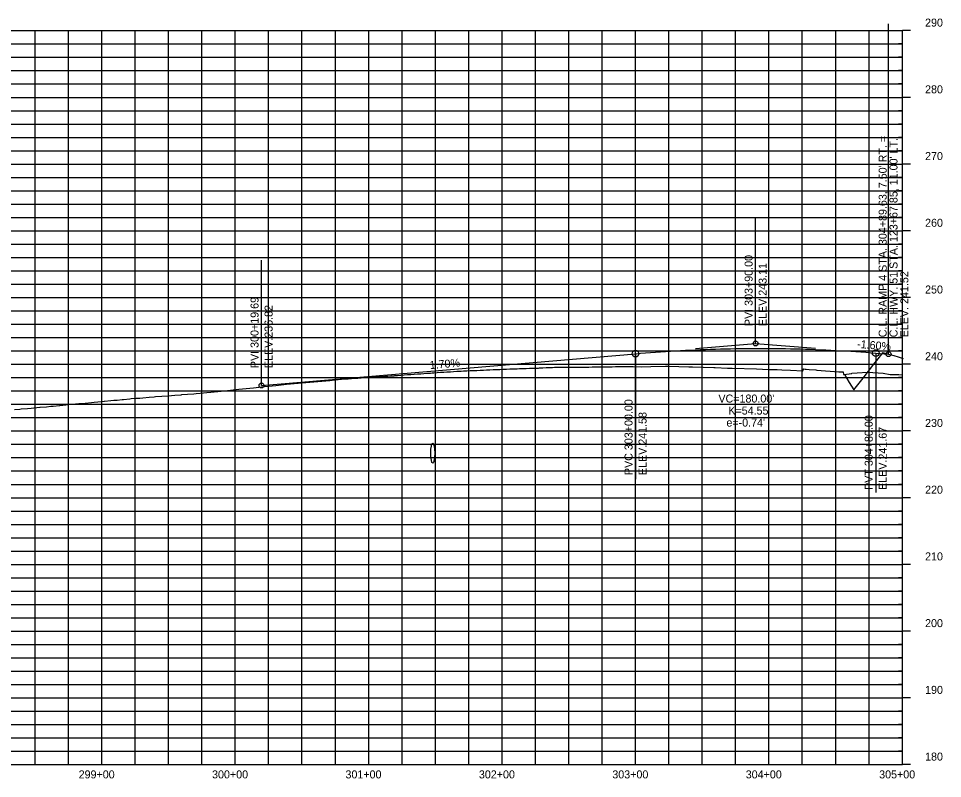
# Model space of a CAD drawing. Extents: x 921603 to 924670, y 1759276 to 1766491.
# Drawn here: x 922277 to 922970, y 1760922 to 1761491 of the extents above; entities that cross this region are included whole.
import ezdxf

# ---------------------------------------------------------------- set-up
doc = ezdxf.new("R2010")
doc.units = 0
for name, color, linetype in [('R_Axis_Annotation', 7, 'Continuous'), ('R_Drainage', 7, 'Continuous'), ('R_Exist Surface', 7, 'Continuous'), ('R_Grid', 7, 'Continuous'), ('R_Grid Annot', 7, 'Continuous'), ('R_Grid_Minor', 7, 'Continuous'), ('R_Prop Surface', 7, 'Continuous'), ('R_Vert Alg', 7, 'Continuous'), ('R_Vert Alg Annot', 7, 'Continuous')]:
    doc.layers.add(name, color=color, linetype=linetype)

msp = doc.modelspace()

# ---------------------------------------------------------------- linework, layer by layer
at = {"layer": 'R_Drainage'}
msp.add_ellipse((922587.83, 1761165.61), major_axis=(0, 7.5), ratio=0.2, dxfattribs=at)
at = {"layer": 'R_Exist Surface'}
msp.add_lwpolyline([(922274.45, 1761198.33), (922278.3, 1761198.63), (922279.25, 1761198.72), (922284.05, 1761199.17), (922286.72, 1761199.41), (922288.85, 1761199.6), (922293.27, 1761199.98), (922293.65, 1761200.02), (922298.45, 1761200.44), (922301.68, 1761200.73), (922303.24, 1761200.86), (922308.04, 1761201.25), (922308.23, 1761201.27), (922312.84, 1761201.8), (922317.37, 1761202.31), (922317.64, 1761202.33), (922322.44, 1761202.73), (922325.06, 1761202.94), (922327.24, 1761203.18), (922332.03, 1761203.7), (922334.06, 1761203.92), (922336.83, 1761204.14), (922341.63, 1761204.52), (922341.88, 1761204.54), (922346.43, 1761205.01), (922348.89, 1761205.27), (922351.23, 1761205.46), (922355.04, 1761205.77), (922356.03, 1761205.87), (922360.83, 1761206.36), (922361.91, 1761206.47), (922365.62, 1761206.76), (922368.2, 1761206.96), (922370.42, 1761207.16), (922375.22, 1761207.57), (922378.91, 1761207.89), (922380.02, 1761207.97), (922384.82, 1761208.31), (922389.39, 1761208.63), (922389.62, 1761208.65), (922394.41, 1761209.05), (922399.21, 1761209.44), (922399.79, 1761209.49), (922404.01, 1761209.78), (922408.81, 1761210.11), (922410.55, 1761210.23), (922413.61, 1761210.52), (922418.41, 1761210.99), (922421.44, 1761211.28), (922431.95, 1761212.38), (922442.41, 1761213.48), (922453.36, 1761214.53), (922461.65, 1761215.6), (922470.16, 1761216.31), (922478.28, 1761217.36), (922486.94, 1761218.08), (922498.77, 1761219.2), (922510.71, 1761220.13), (922514.45, 1761220.5), (922516.92, 1761220.74), (922519.39, 1761220.97), (922521.87, 1761221.2), (922523.66, 1761221.36), (922524.34, 1761221.41), (922526.81, 1761221.59), (922529.29, 1761221.76), (922531.76, 1761221.92), (922533.01, 1761222), (922534.23, 1761222.09), (922536.71, 1761222.26), (922539.18, 1761222.42), (922541.17, 1761222.54), (922541.66, 1761222.58), (922544.13, 1761222.77), (922546.14, 1761222.93), (922546.6, 1761222.95), (922549.08, 1761223.09), (922551.55, 1761223.22), (922554.02, 1761223.35), (922554.12, 1761223.35), (922556.5, 1761223.51), (922558.97, 1761223.68), (922559.3, 1761223.7), (922561.44, 1761223.88), (922563.92, 1761224.09), (922566.39, 1761224.29), (922568.86, 1761224.49), (922571.01, 1761224.66), (922571.34, 1761224.68), (922573.81, 1761224.85), (922576.28, 1761225.02), (922578.76, 1761225.18), (922578.96, 1761225.19), (922581.23, 1761225.35), (922583.7, 1761225.52), (922586.18, 1761225.68), (922587.3, 1761225.75), (922588.65, 1761225.85), (922591.12, 1761226.03), (922593.6, 1761226.2), (922596.07, 1761226.37), (922598.31, 1761226.51), (922598.54, 1761226.53), (922601.02, 1761226.69), (922603.49, 1761226.85), (922605.96, 1761227), (922608.44, 1761227.14), (922609.06, 1761227.17), (922610.91, 1761227.26), (922613.38, 1761227.37), (922615.86, 1761227.47), (922618.33, 1761227.57), (922620.25, 1761227.64), (922620.8, 1761227.66), (922623.28, 1761227.78), (922625.75, 1761227.89), (922628.22, 1761228), (922630.32, 1761228.08), (922630.7, 1761228.1), (922633.17, 1761228.22), (922635.65, 1761228.33), (922638.12, 1761228.43), (922640.59, 1761228.53), (922640.7, 1761228.53), (922643.07, 1761228.62), (922645.54, 1761228.71), (922648.01, 1761228.79), (922650.49, 1761228.87), (922650.98, 1761228.88), (922652.96, 1761228.96), (922655.43, 1761229.05), (922657.91, 1761229.13), (922660.38, 1761229.21), (922660.98, 1761229.22), (922662.85, 1761229.29), (922665.33, 1761229.37), (922667.06, 1761229.42), (922667.8, 1761229.46), (922670.27, 1761229.58), (922672.75, 1761229.7), (922675.22, 1761229.81), (922677.69, 1761229.92), (922678.96, 1761229.97), (922680.17, 1761229.98), (922682.64, 1761230.01), (922685.11, 1761230.02), (922685.44, 1761230.02), (922687.59, 1761230.03), (922690.06, 1761230.02), (922692.53, 1761230.01), (922692.94, 1761230.01), (922695.01, 1761230.04), (922697.48, 1761230.08), (922699.95, 1761230.11), (922702.43, 1761230.13), (922703.88, 1761230.14), (922704.9, 1761230.18), (922707.37, 1761230.27), (922709.85, 1761230.36), (922711.27, 1761230.4), (922712.32, 1761230.41), (922714.79, 1761230.41), (922717.27, 1761230.41), (922719.74, 1761230.4), (922720.75, 1761230.39), (922722.21, 1761230.44), (922724.69, 1761230.52), (922727.16, 1761230.59), (922728.64, 1761230.63), (922729.64, 1761230.62), (922732.11, 1761230.58), (922734.58, 1761230.54), (922737.99, 1761230.48), (922744.1, 1761230.28), (922751.33, 1761230.45), (922762.37, 1761230.76), (922764.89, 1761230.82), (922779.89, 1761230.35), (922782.45, 1761230.38), (922798.43, 1761229.84), (922799.55, 1761229.82), (922808.81, 1761229.39), (922812.17, 1761229.35), (922830.59, 1761228.79), (922834.92, 1761228.69), (922840.21, 1761228.21), (922846.06, 1761228.27), (922849.57, 1761228.18), (922856.03, 1761227.91), (922865.28, 1761227.39), (922865.68, 1761228.57), (922865.79, 1761228.75), (922866.07, 1761228.76), (922867.04, 1761228.6), (922867.65, 1761228.55), (922870, 1761228.37), (922874.98, 1761228.02), (922875.78, 1761227.86), (922892.18, 1761226.66), (922894.38, 1761226.49), (922894.97, 1761226.48), (922895.42, 1761226.46), (922895.47, 1761226.44), (922895.7, 1761224.9), (922895.73, 1761224.68), (922895.89, 1761224.56), (922895.9, 1761224.56), (922901.91, 1761225.44), (922902.05, 1761225.46), (922905.94, 1761225.77), (922913.61, 1761226.37), (922913.98, 1761226.33), (922925.5, 1761225.48), (922930.73, 1761224.69), (922931.27, 1761224.56), (922931.35, 1761224.57), (922931.52, 1761224.65), (922931.7, 1761224.64), (922937.09, 1761224.53), (922939.83, 1761224.4)], dxfattribs=at)
at = {"layer": 'R_Grid'}
for p, q in [((921639.83, 1761482.26), (922939.83, 1761482.26)), ((921639.83, 1761482.26), (922939.83, 1761482.26)), ((922339.83, 1760932.26), (922339.83, 1761482.26)), ((922439.83, 1760932.26), (922439.83, 1761482.26)), ((922539.83, 1760932.26), (922539.83, 1761482.26)), ((922639.83, 1760932.26), (922639.83, 1761482.26)), ((922739.83, 1760932.26), (922739.83, 1761482.26)), ((922839.83, 1760932.26), (922839.83, 1761482.26)), ((922939.83, 1760932.26), (922939.83, 1761482.26)), ((921639.83, 1761432.26), (922939.83, 1761432.26)), ((921639.83, 1761382.26), (922939.83, 1761382.26)), ((921639.83, 1761332.26), (922939.83, 1761332.26)), ((921639.83, 1761282.26), (922939.83, 1761282.26)), ((921639.83, 1761232.26), (922939.83, 1761232.26)), ((921639.83, 1761182.26), (922939.83, 1761182.26)), ((921639.83, 1761132.26), (922939.83, 1761132.26)), ((921639.83, 1761082.26), (922939.83, 1761082.26)), ((921639.83, 1761032.26), (922939.83, 1761032.26)), ((921639.83, 1760982.26), (922939.83, 1760982.26)), ((921639.83, 1760932.26), (922939.83, 1760932.26))]:
    msp.add_line(p, q, dxfattribs=at)
at = {"layer": 'R_Grid Annot'}
for p, q in [((922945.83, 1761482.26), (922939.83, 1761482.26)), ((922945.83, 1761482.26), (922939.83, 1761482.26)), ((922939.83, 1761472.26), (922936.83, 1761472.26)), ((922939.83, 1761462.26), (922936.83, 1761462.26)), ((922939.83, 1761452.26), (922936.83, 1761452.26)), ((922939.83, 1761442.26), (922936.83, 1761442.26)), ((922945.83, 1761432.26), (922939.83, 1761432.26)), ((922939.83, 1761422.26), (922936.83, 1761422.26)), ((922939.83, 1761412.26), (922936.83, 1761412.26)), ((922939.83, 1761402.26), (922936.83, 1761402.26)), ((922939.83, 1761392.26), (922936.83, 1761392.26)), ((922945.83, 1761382.26), (922939.83, 1761382.26)), ((922939.83, 1761372.26), (922936.83, 1761372.26)), ((922939.83, 1761362.26), (922936.83, 1761362.26)), ((922939.83, 1761352.26), (922936.83, 1761352.26)), ((922939.83, 1761342.26), (922936.83, 1761342.26)), ((922945.83, 1761332.26), (922939.83, 1761332.26)), ((922939.83, 1761322.26), (922936.83, 1761322.26)), ((922939.83, 1761312.26), (922936.83, 1761312.26)), ((922939.83, 1761302.26), (922936.83, 1761302.26)), ((922939.83, 1761292.26), (922936.83, 1761292.26)), ((922945.83, 1761282.26), (922939.83, 1761282.26)), ((922939.83, 1761272.26), (922936.83, 1761272.26)), ((922939.83, 1761262.26), (922936.83, 1761262.26)), ((922939.83, 1761252.26), (922936.83, 1761252.26)), ((922939.83, 1761242.26), (922936.83, 1761242.26)), ((922945.83, 1761232.26), (922939.83, 1761232.26)), ((922939.83, 1761222.26), (922936.83, 1761222.26)), ((922939.83, 1761212.26), (922936.83, 1761212.26)), ((922939.83, 1761202.26), (922936.83, 1761202.26)), ((922939.83, 1761192.26), (922936.83, 1761192.26)), ((922945.83, 1761182.26), (922939.83, 1761182.26)), ((922939.83, 1761172.26), (922936.83, 1761172.26)), ((922939.83, 1761162.26), (922936.83, 1761162.26)), ((922939.83, 1761152.26), (922936.83, 1761152.26)), ((922939.83, 1761142.26), (922936.83, 1761142.26)), ((922945.83, 1761132.26), (922939.83, 1761132.26)), ((922939.83, 1761122.26), (922936.83, 1761122.26)), ((922939.83, 1761112.26), (922936.83, 1761112.26)), ((922939.83, 1761102.26), (922936.83, 1761102.26)), ((922939.83, 1761092.26), (922936.83, 1761092.26)), ((922945.83, 1761082.26), (922939.83, 1761082.26)), ((922939.83, 1761072.26), (922936.83, 1761072.26)), ((922939.83, 1761062.26), (922936.83, 1761062.26)), ((922939.83, 1761052.26), (922936.83, 1761052.26)), ((922939.83, 1761042.26), (922936.83, 1761042.26)), ((922945.83, 1761032.26), (922939.83, 1761032.26)), ((922939.83, 1761022.26), (922936.83, 1761022.26)), ((922939.83, 1761012.26), (922936.83, 1761012.26)), ((922939.83, 1761002.26), (922936.83, 1761002.26)), ((922939.83, 1760992.26), (922936.83, 1760992.26)), ((922945.83, 1760982.26), (922939.83, 1760982.26)), ((922939.83, 1760972.26), (922936.83, 1760972.26)), ((922939.83, 1760962.26), (922936.83, 1760962.26)), ((922939.83, 1760952.26), (922936.83, 1760952.26)), ((922939.83, 1760942.26), (922936.83, 1760942.26)), ((922945.83, 1760932.26), (922939.83, 1760932.26))]:
    msp.add_line(p, q, dxfattribs=at)
at = {"layer": 'R_Grid_Minor'}
for p, q in [((922289.83, 1760932.26), (922289.83, 1761482.26)), ((922314.83, 1760932.26), (922314.83, 1761482.26)), ((922364.83, 1760932.26), (922364.83, 1761482.26)), ((922389.83, 1760932.26), (922389.83, 1761482.26)), ((922414.83, 1760932.26), (922414.83, 1761482.26)), ((922464.83, 1760932.26), (922464.83, 1761482.26)), ((922489.83, 1760932.26), (922489.83, 1761482.26)), ((922514.83, 1760932.26), (922514.83, 1761482.26)), ((922564.83, 1760932.26), (922564.83, 1761482.26)), ((922589.83, 1760932.26), (922589.83, 1761482.26)), ((922614.83, 1760932.26), (922614.83, 1761482.26)), ((922664.83, 1760932.26), (922664.83, 1761482.26)), ((922689.83, 1760932.26), (922689.83, 1761482.26)), ((922714.83, 1760932.26), (922714.83, 1761482.26)), ((922764.83, 1760932.26), (922764.83, 1761482.26)), ((922789.83, 1760932.26), (922789.83, 1761482.26)), ((922814.83, 1760932.26), (922814.83, 1761482.26)), ((922864.83, 1760932.26), (922864.83, 1761482.26)), ((922889.83, 1760932.26), (922889.83, 1761482.26)), ((922914.83, 1760932.26), (922914.83, 1761482.26)), ((921639.83, 1761472.26), (922939.83, 1761472.26)), ((921639.83, 1761462.26), (922939.83, 1761462.26)), ((921639.83, 1761452.26), (922939.83, 1761452.26)), ((921639.83, 1761442.26), (922939.83, 1761442.26)), ((921639.83, 1761422.26), (922939.83, 1761422.26)), ((921639.83, 1761412.26), (922939.83, 1761412.26)), ((921639.83, 1761402.26), (922939.83, 1761402.26)), ((921639.83, 1761392.26), (922939.83, 1761392.26)), ((921639.83, 1761372.26), (922939.83, 1761372.26)), ((921639.83, 1761362.26), (922939.83, 1761362.26)), ((921639.83, 1761352.26), (922939.83, 1761352.26)), ((921639.83, 1761342.26), (922939.83, 1761342.26)), ((921639.83, 1761322.26), (922939.83, 1761322.26)), ((921639.83, 1761312.26), (922939.83, 1761312.26)), ((921639.83, 1761302.26), (922939.83, 1761302.26)), ((921639.83, 1761292.26), (922939.83, 1761292.26)), ((921639.83, 1761272.26), (922939.83, 1761272.26)), ((921639.83, 1761262.26), (922939.83, 1761262.26)), ((921639.83, 1761252.26), (922939.83, 1761252.26)), ((921639.83, 1761242.26), (922939.83, 1761242.26)), ((921639.83, 1761222.26), (922939.83, 1761222.26)), ((921639.83, 1761212.26), (922939.83, 1761212.26)), ((921639.83, 1761202.26), (922939.83, 1761202.26)), ((921639.83, 1761192.26), (922939.83, 1761192.26)), ((921639.83, 1761172.26), (922939.83, 1761172.26)), ((921639.83, 1761162.26), (922939.83, 1761162.26)), ((921639.83, 1761152.26), (922939.83, 1761152.26)), ((921639.83, 1761142.26), (922939.83, 1761142.26)), ((921639.83, 1761122.26), (922939.83, 1761122.26)), ((921639.83, 1761112.26), (922939.83, 1761112.26)), ((921639.83, 1761102.26), (922939.83, 1761102.26)), ((921639.83, 1761092.26), (922939.83, 1761092.26)), ((921639.83, 1761072.26), (922939.83, 1761072.26)), ((921639.83, 1761062.26), (922939.83, 1761062.26)), ((921639.83, 1761052.26), (922939.83, 1761052.26)), ((921639.83, 1761042.26), (922939.83, 1761042.26)), ((921639.83, 1761022.26), (922939.83, 1761022.26)), ((921639.83, 1761012.26), (922939.83, 1761012.26)), ((921639.83, 1761002.26), (922939.83, 1761002.26)), ((921639.83, 1760992.26), (922939.83, 1760992.26)), ((921639.83, 1760972.26), (922939.83, 1760972.26)), ((921639.83, 1760962.26), (922939.83, 1760962.26)), ((921639.83, 1760952.26), (922939.83, 1760952.26)), ((921639.83, 1760942.26), (922939.83, 1760942.26))]:
    msp.add_line(p, q, dxfattribs=at)
at = {"layer": 'R_Prop Surface'}
msp.add_lwpolyline([(922896.32, 1761224.63), (922899.98, 1761218.62), (922903.36, 1761213.07), (922910.37, 1761221.93), (922919.28, 1761233.22), (922920.77, 1761235.1), (922925.44, 1761241.02), (922926.01, 1761240.85), (922929.46, 1761239.86), (922933.34, 1761238.74), (922936.76, 1761237.76), (922940.5, 1761236.68)], dxfattribs=at)
at = {"layer": 'R_Vert Alg'}
for p, q in [((922459.52, 1761216.35), (922739.83, 1761240.18)), ((922919.83, 1761240.63), (922929.46, 1761239.86))]:
    msp.add_line(p, q, dxfattribs=at)
msp.add_lwpolyline([(922739.83, 1761240.18), (922743.58, 1761240.49), (922747.33, 1761240.79), (922751.08, 1761241.08), (922754.83, 1761241.35), (922758.58, 1761241.61), (922762.33, 1761241.86), (922766.08, 1761242.1), (922769.83, 1761242.32), (922773.58, 1761242.53), (922777.33, 1761242.72), (922781.08, 1761242.91), (922784.83, 1761243.08), (922788.58, 1761243.23), (922792.33, 1761243.38), (922796.08, 1761243.51), (922799.83, 1761243.63), (922803.58, 1761243.74), (922807.33, 1761243.83), (922811.08, 1761243.91), (922814.83, 1761243.98), (922818.58, 1761244.03), (922822.33, 1761244.07), (922826.08, 1761244.1), (922833.58, 1761244.12), (922837.33, 1761244.11), (922841.08, 1761244.09), (922844.83, 1761244.05), (922848.58, 1761244), (922852.33, 1761243.94), (922856.08, 1761243.87), (922859.83, 1761243.78), (922863.58, 1761243.68), (922867.33, 1761243.57), (922871.08, 1761243.44), (922874.83, 1761243.3), (922878.58, 1761243.15), (922882.33, 1761242.99), (922886.08, 1761242.81), (922889.83, 1761242.62), (922893.58, 1761242.41), (922897.33, 1761242.2), (922901.08, 1761241.97), (922904.83, 1761241.73), (922908.58, 1761241.47), (922912.33, 1761241.2), (922916.08, 1761240.92), (922919.83, 1761240.63)], dxfattribs=at)
at = {"layer": 'R_Vert Alg Annot'}
for p, q in [((922929.46, 1761249.86), (922929.46, 1761487.35)), ((922829.83, 1761257.83), (922829.83, 1761341.83)), ((922459.52, 1761226.35), (922459.52, 1761310.35)), ((922829.83, 1761247.83), (922829.83, 1761257.83)), ((922784.83, 1761244), (922829.83, 1761247.83)), ((922829.83, 1761247.83), (922874.83, 1761244.23)), ((922929.46, 1761239.86), (922929.46, 1761249.86)), ((922739.83, 1761240.18), (922739.83, 1761230.18)), ((922919.83, 1761240.63), (922919.83, 1761230.63)), ((922459.52, 1761216.35), (922459.52, 1761226.35)), ((922739.83, 1761230.18), (922739.83, 1761146.18)), ((922919.83, 1761230.63), (922919.83, 1761136.25))]:
    msp.add_line(p, q, dxfattribs=at)
for centre, radius in [((922829.83, 1761247.83), 1.85), ((922739.83, 1761240.18), 2.5), ((922919.83, 1761240.63), 2.5), ((922929.46, 1761239.86), 1.85), ((922459.52, 1761216.35), 1.85)]:
    msp.add_circle(centre, radius, dxfattribs=at)

# ---------------------------------------------------------------- texts
at = {"layer": 'R_Axis_Annotation'}
for s, p in [('290', (922956.84, 1761485.26)), ('290', (922956.84, 1761485.26)), ('280', (922956.84, 1761435.26)), ('270', (922956.84, 1761385.26)), ('260', (922956.84, 1761335.26)), ('250', (922956.84, 1761285.26)), ('240', (922956.84, 1761235.26)), ('230', (922956.84, 1761185.26)), ('220', (922956.84, 1761135.26)), ('210', (922956.84, 1761085.26)), ('200', (922956.84, 1761035.26)), ('190', (922956.84, 1760985.26)), ('180', (922956.84, 1760935.26)), ('299+00', (922322.42, 1760921.91)), ('300+00', (922422.42, 1760921.91)), ('301+00', (922522.42, 1760921.91)), ('302+00', (922622.42, 1760921.91)), ('303+00', (922722.42, 1760921.91)), ('304+00', (922822.42, 1760921.91)), ('305+00', (922922.42, 1760921.91))]:
    msp.add_text(s, height=6, dxfattribs=at).set_placement(p)
at = {"layer": 'R_Vert Alg Annot'}
for s, rotation, p in [("C.L. RAMP 4 STA. 304+89.63, 7.50' RT. =", 90, (922928.05, 1761252.44)), ("C.L. HWY. 51 STA. 123+67.85, 11.00' LT.", 90, (922936.18, 1761252.44)), ('PVI 303+90.00', 90, (922827.58, 1761260.83)), ('ELEV.243.11', 90, (922838.08, 1761260.83)), ('ELEV. 241.52', 90, (922944.3, 1761252.44)), ('PVI 300+19.69', 90, (922457.27, 1761229.35)), ('ELEV.236.82', 90, (922467.77, 1761229.35)), ('-1.60%', 355.42608, (922905.72, 1761244.54)), ('1.70%', 4.85846, (922585.8, 1761228.59)), ('PVC 303+00.00', 90, (922737.58, 1761149.18)), ('ELEV.241.58', 90, (922748.08, 1761149.18)), ('PVT 304+80.00', 90, (922917.58, 1761138.07)), ('ELEV.241.67', 90, (922928.08, 1761138.07))]:
    msp.add_text(s, height=6, rotation=rotation, dxfattribs=at).set_placement(p)
for s, p in [("VC=180.00'", (922801.93, 1761203.55)), ('K=54.55', (922809.37, 1761194.55)), ("e=-0.74'", (922807.93, 1761185.55))]:
    msp.add_text(s, height=6, dxfattribs=at).set_placement(p)

doc.saveas('drawing.dxf')
